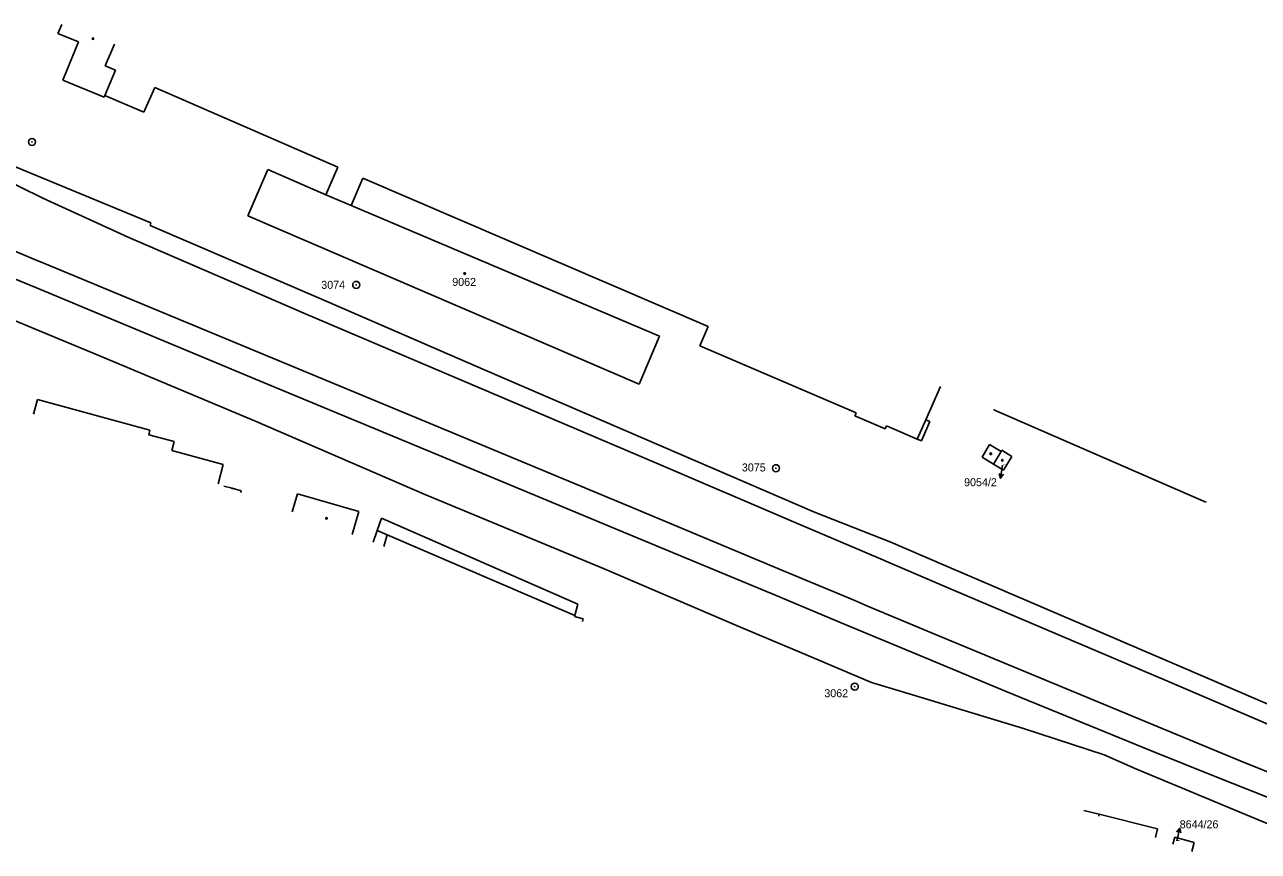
# Model space of a CAD drawing. Extents: x -825057 to -819383, y -1071633 to -1067888.
# Drawn here: x -824095 to -823833, y -1070146.2 to -1069970.6 of the extents above; entities that cross this region are included whole.
import ezdxf

# ---------------------------------------------------------------- set-up
doc = ezdxf.new("R2010")
doc.units = 0
for name, color, linetype in [('Vrstva 1', 7, 'Continuous'), ('Vrstva 10', 7, 'Continuous'), ('Vrstva 16', 7, 'Continuous'), ('Vrstva 17', 7, 'Continuous'), ('Vrstva 19', 7, 'Continuous'), ('Vrstva 24', 7, 'Continuous'), ('Vrstva 25', 7, 'Continuous'), ('Vrstva 4', 7, 'Continuous')]:
    doc.layers.add(name, color=color, linetype=linetype)

msp = doc.modelspace()

# ---------------------------------------------------------------- linework, layer by layer
at = {"layer": 'Vrstva 1'}
for p, q in [((-824087.12, -1069970.6), (-824087.93, -1069972.45)), ((-824087.93, -1069972.45), (-824083.56, -1069974.24)), ((-824083.56, -1069974.24), (-824086.9, -1069982.4)), ((-824086.9, -1069982.4), (-824078.12, -1069985.99)), ((-824078.12, -1069985.99), (-824077.99, -1069985.67)), ((-824077.99, -1069985.67), (-824069.67, -1069989.16)), ((-824069.67, -1069989.16), (-824067.32, -1069983.94)), ((-824067.32, -1069983.94), (-824028.47, -1070000.85)), ((-824068.23, -1070012.7), (-824105.53, -1069997.27)), ((-824043.39, -1070001.33), (-824047.61, -1070011.22)), ((-824031.01, -1070006.75), (-824043.39, -1070001.33)), ((-824028.47, -1070000.85), (-824031.01, -1070006.75)), ((-824025.65, -1070009.04), (-824023.15, -1070003.2)), ((-824023.15, -1070003.2), (-823949.82, -1070034.69)), ((-824031.01, -1070006.75), (-824025.65, -1070009.04)), ((-823960.16, -1070036.8), (-824025.65, -1070009.04)), ((-824047.61, -1070011.22), (-823964.48, -1070046.95)), ((-824068.34, -1070013.29), (-824068.23, -1070012.7)), ((-824032.59, -1070028.59), (-824068.34, -1070013.29)), ((-824078.38, -1070041.26), (-824109.95, -1070028.12)), ((-823997.23, -1070044.01), (-824032.59, -1070028.59)), ((-823949.82, -1070034.69), (-823951.62, -1070038.85)), ((-823964.48, -1070046.95), (-823960.16, -1070036.8)), ((-823951.62, -1070038.85), (-823918.43, -1070053.07)), ((-824045.86, -1070054.86), (-824078.38, -1070041.26)), ((-823959.77, -1070060.15), (-823997.23, -1070044.01)), ((-823903.65, -1070054.53), (-823900.53, -1070047.44)), ((-824092.26, -1070050.23), (-824093.11, -1070053.33)), ((-824068.39, -1070056.76), (-824092.26, -1070050.23)), ((-823918.43, -1070053.07), (-823918.7, -1070053.71)), ((-823918.7, -1070053.71), (-823912.26, -1070056.47)), ((-823889.19, -1070052.35), (-823889.2, -1070052.39)), ((-823889.2, -1070052.39), (-823844.16, -1070072)), ((-824010.15, -1070070.3), (-824045.86, -1070054.86)), ((-823912.26, -1070056.47), (-823911.99, -1070055.82)), ((-823911.99, -1070055.82), (-823905.46, -1070058.62)), ((-823904.57, -1070059.01), (-823902.76, -1070054.92)), ((-823902.76, -1070054.92), (-823903.65, -1070054.53)), ((-824068.64, -1070057.7), (-824068.39, -1070056.76)), ((-824063.24, -1070059.17), (-824068.64, -1070057.7)), ((-824063.75, -1070061.04), (-824063.24, -1070059.17)), ((-823905.46, -1070058.62), (-823904.57, -1070059.01)), ((-824052.81, -1070064.02), (-824063.75, -1070061.04)), ((-823927.27, -1070074.15), (-823959.77, -1070060.15)), ((-823891.68, -1070062.45), (-823890.1, -1070059.81)), ((-823890.1, -1070059.81), (-823887.63, -1070061.26)), ((-823887.63, -1070061.26), (-823887.48, -1070061.01)), ((-823887.48, -1070061.01), (-823885.36, -1070062.31)), ((-824053.93, -1070068.13), (-824052.81, -1070064.02)), ((-823889.29, -1070063.92), (-823891.68, -1070062.45)), ((-823887.14, -1070065.24), (-823889.29, -1070063.92)), ((-823885.36, -1070062.31), (-823887.14, -1070065.24)), ((-824050.96, -1070069.06), (-824052.68, -1070068.6)), ((-824048.99, -1070069.6), (-824050.96, -1070069.06)), ((-824049.09, -1070069.95), (-824048.99, -1070069.6)), ((-824038.16, -1070074.08), (-824037.07, -1070070.25)), ((-824037.07, -1070070.25), (-824024.06, -1070073.99)), ((-823971.96, -1070086.15), (-824010.15, -1070070.3)), ((-823844.16, -1070072), (-823844.1, -1070071.88)), ((-824024.06, -1070073.99), (-824025.47, -1070078.86)), ((-823911.04, -1070080.51), (-823927.27, -1070074.15)), ((-824020.16, -1070078.05), (-824019.25, -1070075.4)), ((-824019.25, -1070075.4), (-823977.5, -1070093.7)), ((-824021.02, -1070080.55), (-824020.16, -1070078.05)), ((-824018, -1070078.98), (-824020.16, -1070078.05)), ((-824018, -1070078.98), (-824018.69, -1070081.43)), ((-823908.42, -1070081.65), (-823911.04, -1070080.51)), ((-823898.75, -1070085.8), (-823908.42, -1070081.65)), ((-823943.82, -1070098.23), (-823971.96, -1070086.15)), ((-823850.43, -1070106.56), (-823898.75, -1070085.8)), ((-823977.5, -1070093.7), (-823978.18, -1070096.1)), ((-823978.18, -1070096.1), (-823978.24, -1070096.3)), ((-823978.24, -1070096.3), (-823976.38, -1070096.82)), ((-823976.38, -1070096.82), (-823976.53, -1070097.34)), ((-823926.52, -1070105.53), (-823943.82, -1070098.23)), ((-823923.98, -1070106.59), (-823926.52, -1070105.53)), ((-823915.16, -1070110.31), (-823923.98, -1070106.59)), ((-823818.96, -1070120.13), (-823850.43, -1070106.56)), ((-823908.83, -1070112.25), (-823915.16, -1070110.31)), ((-823882.9, -1070120.13), (-823908.83, -1070112.25)), ((-823865.79, -1070125.71), (-823882.9, -1070120.13)), ((-823859, -1070128.68), (-823865.79, -1070125.71)), ((-823827.74, -1070141.66), (-823859, -1070128.68)), ((-823870.08, -1070137.52), (-823866.83, -1070138.33)), ((-823866.83, -1070138.33), (-823854.4, -1070141.42)), ((-823854.4, -1070141.42), (-823854.87, -1070143.26)), ((-823851.15, -1070144.67), (-823850.77, -1070143.21)), ((-823850.77, -1070143.21), (-823846.62, -1070144.28)), ((-823846.62, -1070144.28), (-823847.11, -1070146.19))]:
    msp.add_line(p, q, dxfattribs=at)
at = {"layer": 'Vrstva 10'}
for p, q in [((-824091.13, -1070007.43), (-824115.86, -1069995.31)), ((-824072.88, -1070015.8), (-824091.13, -1070007.43)), ((-824093.03, -1070020.38), (-824116.39, -1070010.68)), ((-824092.51, -1070026.49), (-824118.46, -1070015.74)), ((-824071.37, -1070016.47), (-824072.88, -1070015.8)), ((-824045.37, -1070027.73), (-824071.37, -1070016.47)), ((-824090.43, -1070021.46), (-824093.03, -1070020.38)), ((-824040.42, -1070042.23), (-824090.43, -1070021.46)), ((-824042.56, -1070047.28), (-824092.51, -1070026.49)), ((-824035.73, -1070031.9), (-824045.37, -1070027.73)), ((-823999.73, -1070047.18), (-824035.73, -1070031.9)), ((-824004.3, -1070057.26), (-824040.42, -1070042.23)), ((-824006.41, -1070062.33), (-824042.56, -1070047.28)), ((-823960.85, -1070063.75), (-823999.73, -1070047.18)), ((-823965.5, -1070073.39), (-824004.3, -1070057.26)), ((-823967.8, -1070078.38), (-824006.41, -1070062.33)), ((-823931.7, -1070076.17), (-823960.85, -1070063.75)), ((-823933.71, -1070086.66), (-823965.5, -1070073.39)), ((-823913.24, -1070084.07), (-823931.7, -1070076.17)), ((-823935.42, -1070091.84), (-823967.8, -1070078.38)), ((-823910.63, -1070085.19), (-823913.24, -1070084.07)), ((-823898.28, -1070090.47), (-823910.63, -1070085.19)), ((-823918.73, -1070092.93), (-823933.71, -1070086.66)), ((-823852.48, -1070110), (-823898.28, -1070090.47)), ((-823921.62, -1070097.62), (-823935.42, -1070091.84)), ((-823916.14, -1070094.02), (-823918.73, -1070092.93)), ((-823901.58, -1070100.11), (-823916.14, -1070094.02)), ((-823919.05, -1070098.69), (-823921.62, -1070097.62)), ((-823905.75, -1070104.26), (-823919.05, -1070098.69)), ((-823854.27, -1070119.76), (-823901.58, -1070100.11)), ((-823886.55, -1070112.23), (-823905.75, -1070104.26)), ((-823820.48, -1070123.67), (-823852.48, -1070110)), ((-823855.92, -1070124.77), (-823886.55, -1070112.23)), ((-823836.87, -1070126.94), (-823854.27, -1070119.76)), ((-823842.18, -1070130.3), (-823855.92, -1070124.77)), ((-823823.85, -1070132.28), (-823836.87, -1070126.94)), ((-823827.54, -1070136.13), (-823842.18, -1070130.3))]:
    msp.add_line(p, q, dxfattribs=at)
at = {"layer": 'Vrstva 16'}
for p, q in [((-823887.34, -1070064.16), (-823887.771, -1070066.947)), ((-823850.32, -1070143.99), (-823849.719, -1070141.296))]:
    msp.add_line(p, q, dxfattribs=at)
for points in [[(-823887.163, -1070066.09), (-823887.771, -1070066.947), (-823888.092, -1070065.946)], [(-823850.368, -1070142.094), (-823849.719, -1070141.296), (-823849.47, -1070142.294)]]:
    msp.add_lwpolyline(points, dxfattribs=at)
at = {"layer": 'Vrstva 24'}
for centre, radius in [((-824093.43, -1069995.51), 0.75), ((-824093.43, -1069995.51), 0.0327), ((-824024.59, -1070025.87), 0.75), ((-824024.59, -1070025.87), 0.0327), ((-823935.46, -1070064.82), 0.75), ((-823935.46, -1070064.82), 0.0327), ((-823918.72, -1070111.21), 0.75), ((-823918.72, -1070111.21), 0.0327)]:
    msp.add_circle(centre, radius, dxfattribs=at)
at = {"layer": 'Vrstva 25'}
for centre in [(-824080.49, -1069973.56), (-824001.57, -1070023.46), (-823889.83, -1070061.75), (-823887.38, -1070063.13), (-824030.9, -1070075.46)]:
    msp.add_circle(centre, 0.175, dxfattribs=at)
at = {"layer": 'Vrstva 4'}
for p, q in [((-824075.93, -1069974.72), (-824077.91, -1069979.32)), ((-824075.7, -1069980.29), (-824077.99, -1069985.67)), ((-824077.91, -1069979.32), (-824075.7, -1069980.29)), ((-823905.46, -1070058.62), (-823903.65, -1070054.53)), ((-823887.63, -1070061.26), (-823889.29, -1070063.92)), ((-824051.01, -1070069.23), (-824050.96, -1070069.06)), ((-823978.18, -1070096.1), (-824018, -1070078.98)), ((-823866.92, -1070138.71), (-823866.83, -1070138.33))]:
    msp.add_line(p, q, dxfattribs=at)

# ---------------------------------------------------------------- texts
at = {"layer": 'Vrstva 16'}
for s, p in [('9054/2', (-823895.504, -1070068.64)), ('8644/26', (-823849.72, -1070141.3))]:
    msp.add_text(s, height=1.7, dxfattribs=at).set_placement(p)
at = {"layer": 'Vrstva 17'}
for s, p in [('3074', (-824032.01, -1070026.71)), ('3075', (-823942.69, -1070065.5)), ('3062', (-823925.184, -1070113.46))]:
    msp.add_text(s, height=1.7, dxfattribs=at).set_placement(p)
at = {"layer": 'Vrstva 19'}
for s, height, p in [('9062', 1.7, (-824004.191, -1070026.09)), ('9054/2', 0.2, (-823887.34, -1070064.16)), ('8644/26', 0.2, (-823850.32, -1070143.99))]:
    msp.add_text(s, height=height, dxfattribs=at).set_placement(p)

doc.saveas('drawing.dxf')
